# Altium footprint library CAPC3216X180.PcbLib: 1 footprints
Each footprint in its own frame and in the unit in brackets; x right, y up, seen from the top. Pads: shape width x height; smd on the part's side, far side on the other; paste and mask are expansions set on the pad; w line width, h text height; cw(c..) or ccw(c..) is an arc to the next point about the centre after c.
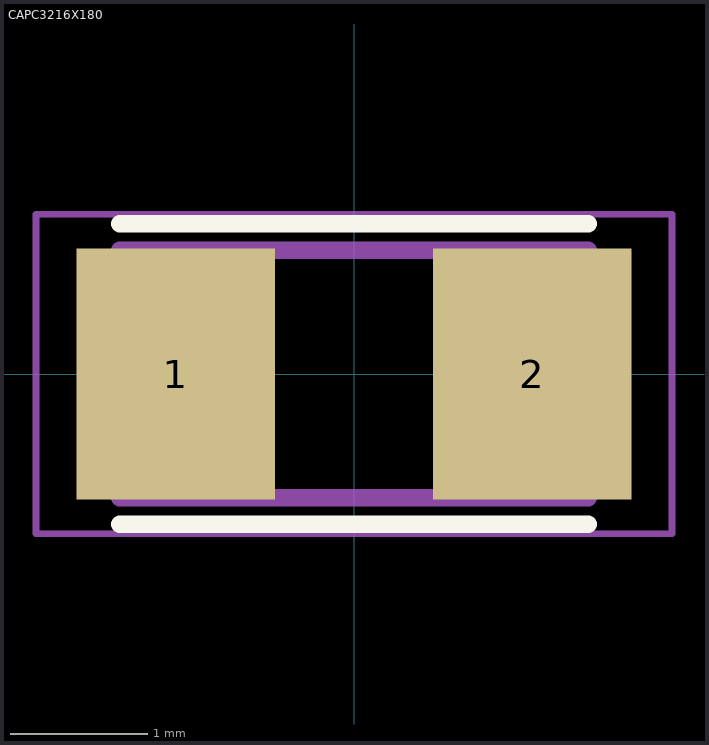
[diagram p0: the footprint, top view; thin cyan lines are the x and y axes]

## CAPC3216X180 [mm]
pads (2):
  rect 1.44x1.82 smd: 1(-1.295,0) 2(1.295,0)
Top Overlay:
  lines w0.127: -1.7,-1.09 1.7,-1.09 ; -1.7,1.09 1.7,1.09
Mechanical 13:
  lines w0.127: -1.7,-0.9 -1.7,0.9 1.7,0.9 1.7,-0.9 -1.7,-0.9
Mechanical 15:
  lines w0.05: -2.31,-1.16 -2.31,1.16 2.31,1.16 2.31,-1.16 -2.31,-1.16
